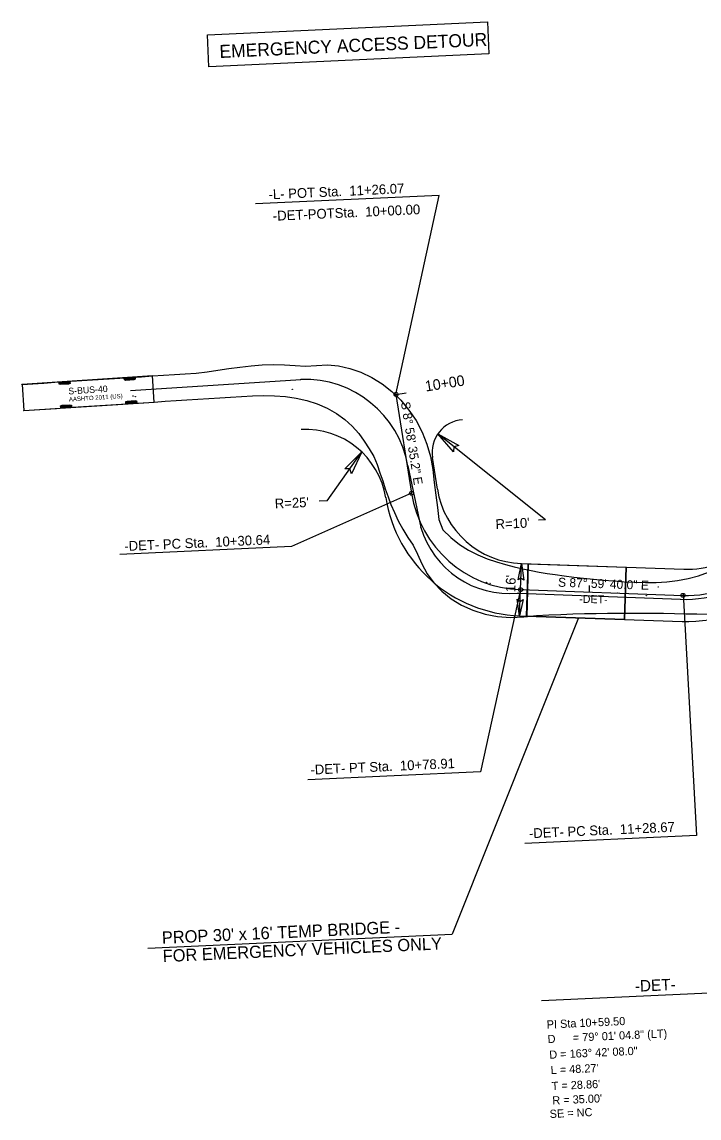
# Model space of a CAD drawing. Extents: x 1191294 to 1803985, y 659552 to 893190.
# Drawn here: x 1191294.4 to 1191501.7, y 892854.1 to 893189.8 of the extents above; entities that cross this region are included whole.
import ezdxf

# ---------------------------------------------------------------- set-up
doc = ezdxf.new("R2010")
doc.units = 0
for name, color, linetype in [('Old_Level_5', 7, 'Continuous'), ('Prop DSN Text', 7, 'Continuous'), ('Prop EOT', 7, 'Continuous'), ('Prop Horizontal Alignment', 7, 'Continuous'), ('Prop Horizontal Alignment Curve and Spiral Data', 7, 'Continuous'), ('Prop Horizontal Alignment Direction Label', 7, 'Continuous'), ('Prop Horizontal Alignment Station Label', 7, 'Continuous'), ('Prop Horizontal Alignment Tick Label', 7, 'Continuous'), ('Prop Horizontal Alignment Tick Large', 7, 'Continuous'), ('Prop Horizontal Alignment Tick Small', 7, 'Continuous'), ('Prop Leader Line Medium', 7, 'Continuous'), ('Prop Roadway Bridge', 7, 'Continuous'), ('Prop Superelevation  Arrow CELL', 7, 'Continuous'), ('Prop Terminator CELL', 7, 'Continuous'), ('Scratch_Level_4', 7, 'Continuous'), ('Scratch_Level_5', 7, 'Continuous'), ('Scratch_Level_9', 7, 'Continuous')]:
    doc.layers.add(name, color=color, linetype=linetype)

msp = doc.modelspace()

# ---------------------------------------------------------------- linework, layer by layer
at = {"layer": 'Old_Level_5'}
msp.add_circle((1191328.43, 893075.21), 0.0417, dxfattribs=at)
at = {"layer": 'Prop DSN Text'}
for p, q in [((1191454.72, 893037.3), (1191421.71, 893063.62)), ((1191387.89, 893043.1), (1191398.43, 893058.11)), ((1191387.89, 893043.1), (1191385.46, 893042.99)), ((1191454.72, 893037.3), (1191452.51, 893037.2))]:
    msp.add_line(p, q, dxfattribs=at)
at = {"layer": 'Prop EOT'}
for p, q in [((1191421.61, 893046.69), (1191420.08, 893056.4)), ((1191447.33, 893023.92), (1191497.07, 893022.18)), ((1191446.78, 893007.93), (1191496.51, 893006.19))]:
    msp.add_line(p, q, dxfattribs=at)
for centre, radius, start, end in [((1191381.15, 893040.04), 25, 9.1923, 92.9116), ((1191429.95, 893057.96), 10, 93.6582, 188.9764), ((1191448.28, 893050.91), 27, 188.9764, 267.9944), ((1191448.28, 893050.91), 43, 188.9764, 267.9944), ((1191498.01, 893049.17), 27, 267.9944, 312.5411), ((1191498.01, 893049.17), 43, 267.9944, 312.5411)]:
    msp.add_arc(centre, radius, start, end, dxfattribs=at)
at = {"layer": 'Prop Horizontal Alignment'}
for p, q in [((1191408.93, 893075.71), (1191413.71, 893045.45)), ((1191447.06, 893015.93), (1191496.79, 893014.19))]:
    msp.add_line(p, q, dxfattribs=at)
for centre, start, end in [((1191448.28, 893050.91), 188.9764, 267.9944), ((1191498.01, 893049.17), 267.9944, 312.5411)]:
    msp.add_arc(centre, 35, start, end, dxfattribs=at)
at = {"layer": 'Prop Horizontal Alignment Station Label'}
for p, q in [((1191422.16, 893136.67), (1191365.93, 893134.1)), ((1191408.93, 893075.71), (1191422.16, 893136.67)), ((1191413.71, 893045.45), (1191376.96, 893029.14)), ((1191376.96, 893029.14), (1191324.41, 893026.74)), ((1191447.06, 893015.93), (1191434.84, 892960.11)), ((1191496.81, 893014.79), (1191500.9, 892940.61)), ((1191434.84, 892960.11), (1191381.98, 892957.69)), ((1191500.9, 892940.61), (1191448.33, 892938.21)), ((1191544.98, 892894.19), (1191453.47, 892890))]:
    msp.add_line(p, q, dxfattribs=at)
msp.add_lwpolyline([(1191351.2, 893185.88), (1191436.93, 893189.8), (1191437.38, 893180.01), (1191351.65, 893176.09)], close=True, dxfattribs=at)
for centre in [(1191408.93, 893075.71), (1191408.93, 893075.71), (1191413.71, 893045.45), (1191447.06, 893015.93), (1191496.79, 893014.19)]:
    msp.add_circle(centre, 0.6, dxfattribs=at)
at = {"layer": 'Prop Horizontal Alignment Tick Large'}
msp.add_line((1191408.93, 893075.71), (1191412.09, 893076.21), dxfattribs=at)
msp.add_line((1191408.93, 893075.71), (1191412.09, 893076.21), dxfattribs=at)
at = {"layer": 'Prop Horizontal Alignment Tick Small'}
msp.add_line((1191468.13, 893015.19), (1191468.2, 893017.19), dxfattribs=at)
at = {"layer": 'Prop Leader Line Medium'}
for p in [(1191464.79, 893007.29), (1191333.01, 892906.14)]:
    msp.add_line(p, (1191426.17, 892910.4), dxfattribs=at)
at = {"layer": 'Prop Roadway Bridge'}
for p, q in [((1191449.43, 893023.85), (1191448.95, 893007.52)), ((1191449.43, 893023.85), (1191479.41, 893022.8)), ((1191478.85, 893006.81), (1191479.41, 893022.8)), ((1191448.87, 893007.86), (1191478.85, 893006.81))]:
    msp.add_line(p, q, dxfattribs=at)
at = {"layer": 'Prop Superelevation  Arrow CELL'}
msp.add_line((1191446.78, 893007.93), (1191447.33, 893023.92), dxfattribs=at)
at = {"layer": 'Prop Terminator CELL'}
for points in [[(1191426.57, 893058.16), (1191421.71, 893063.62), (1191428.17, 893060.11), (1191426.65, 893059.68)], [(1191393.28, 893052.93), (1191398.43, 893058.11), (1191395.32, 893051.45), (1191394.8, 893052.94)], [(1191446.29, 893018.92), (1191447.33, 893023.92), (1191448.05, 893018.83), (1191447.18, 893019.5)], [(1191447.82, 893012.94), (1191446.78, 893007.93), (1191446.06, 893013.03), (1191446.93, 893012.35)]]:
    msp.add_lwpolyline(points, close=True, dxfattribs=at)
at = {"layer": 'Scratch_Level_4'}
msp.add_lwpolyline([(1191449.43, 893023.85), (1191479.41, 893022.8), (1191478.85, 893006.81), (1191448.87, 893007.86)], close=True, dxfattribs=at)
at = {"layer": 'Scratch_Level_5'}
for centre in [(1191329.17, 893075.06), (1191377.19, 893077.26), (1191377.19, 893077.26), (1191436.68, 893018.19), (1191436.68, 893018.19), (1191437.73, 893017.83), (1191437.73, 893017.83), (1191448.04, 893015.89), (1191448.04, 893015.89), (1191476.79, 893014.89), (1191476.79, 893014.89), (1191489.23, 893016.71), (1191489.23, 893016.71)]:
    msp.add_circle(centre, 0.0417, dxfattribs=at)
at = {"layer": 'Scratch_Level_9'}
for p, q in [((1191334.39, 893081.38), (1191294.47, 893078.79)), ((1191294.47, 893078.79), (1191294.99, 893070.81)), ((1191309.12, 893079.53), (1191305.79, 893079.32)), ((1191309.13, 893079.32), (1191305.81, 893079.11)), ((1191309.15, 893079.12), (1191305.82, 893078.9)), ((1191329.08, 893080.83), (1191325.75, 893080.61)), ((1191329.09, 893080.62), (1191325.76, 893080.4)), ((1191329.1, 893080.41), (1191325.78, 893080.19)), ((1191327.66, 893076.93), (1191379.85, 893080.32)), ((1191334.9, 893073.39), (1191334.39, 893081.38)), ((1191334.39, 893081.38), (1191334.39, 893081.38)), ((1191294.99, 893070.81), (1191334.9, 893073.39)), ((1191309.58, 893072.38), (1191306.26, 893072.17)), ((1191309.6, 893072.17), (1191306.27, 893071.96)), ((1191309.61, 893071.96), (1191306.28, 893071.75)), ((1191329.54, 893073.67), (1191326.21, 893073.46)), ((1191329.55, 893073.47), (1191326.23, 893073.25)), ((1191329.57, 893073.26), (1191326.24, 893073.04)), ((1191412.6, 893053.85), (1191416.58, 893034.98)), ((1191446.3, 893014.87), (1191496.01, 893012.99))]:
    msp.add_line(p, q, dxfattribs=at)
for points in [[(1191294.47, 893078.79), (1191297.8, 893079.01), (1191301.12, 893079.22), (1191304.45, 893079.44), (1191307.77, 893079.65), (1191311.1, 893079.87), (1191314.43, 893080.08), (1191317.75, 893080.3), (1191321.08, 893080.52), (1191324.41, 893080.73), (1191327.73, 893080.95), (1191331.06, 893081.16), (1191334.39, 893081.38), (1191334.39, 893081.38), (1191337.73, 893081.59), (1191341.08, 893081.81), (1191344.42, 893082.03), (1191347.77, 893082.27), (1191351.1, 893082.67), (1191354.44, 893083.12), (1191357.8, 893083.63), (1191361.18, 893084.1), (1191364.58, 893084.49), (1191368.01, 893084.76), (1191371.43, 893084.88), (1191374.8, 893084.83), (1191378.02, 893084.53), (1191381.23, 893084.41), (1191384.57, 893084.63), (1191387.93, 893084.76), (1191391.36, 893084.44), (1191394.8, 893083.68), (1191398.2, 893082.49), (1191401.5, 893080.91), (1191404.67, 893078.93), (1191407.65, 893076.59), (1191410.4, 893073.92), (1191412.88, 893070.95), (1191415.06, 893067.7), (1191416.91, 893064.21), (1191418.39, 893060.53), (1191419.49, 893056.69), (1191420.19, 893052.74), (1191420.66, 893048.77), (1191421.14, 893044.91), (1191421.61, 893041.14), (1191422.09, 893037.45), (1191423.32, 893034.3), (1191425.72, 893031.86), (1191428.34, 893029.74), (1191431.15, 893027.99), (1191434.02, 893026.57), (1191436.89, 893025.4), (1191439.7, 893024.42), (1191442.46, 893023.59), (1191445.14, 893022.89), (1191447.75, 893022.29), (1191450.29, 893021.77), (1191452.77, 893021.31), (1191455.19, 893020.91), (1191457.68, 893020.53), (1191460.45, 893020.15), (1191463.34, 893019.8), (1191466.33, 893019.47), (1191469.38, 893019.16), (1191472.49, 893018.87), (1191475.64, 893018.61), (1191478.83, 893018.37), (1191482.05, 893018.18), (1191485.3, 893018.08), (1191488.56, 893018.12), (1191491.83, 893018.31), (1191495.09, 893018.7), (1191498.33, 893019.3), (1191501.52, 893020.14), (1191504.63, 893021.24)], [(1191294.99, 893070.81), (1191298.31, 893071.02), (1191301.64, 893071.24), (1191304.97, 893071.46), (1191308.29, 893071.67), (1191311.62, 893071.89), (1191314.94, 893072.1), (1191318.27, 893072.32), (1191321.6, 893072.53), (1191324.92, 893072.75), (1191328.25, 893072.96), (1191331.58, 893073.18), (1191334.9, 893073.39), (1191334.9, 893073.39), (1191334.9, 893073.39), (1191338.25, 893073.61), (1191341.59, 893073.83), (1191344.94, 893074.05), (1191348.29, 893074.26), (1191351.63, 893074.48), (1191354.98, 893074.7), (1191358.32, 893074.91), (1191361.67, 893075.13), (1191365.02, 893075.3), (1191368.37, 893075.37), (1191371.72, 893075.31), (1191375.06, 893075.05), (1191378.38, 893074.57), (1191381.64, 893073.83), (1191384.83, 893072.8), (1191387.88, 893071.47), (1191390.71, 893069.87), (1191393.27, 893068.02), (1191395.54, 893065.96), (1191397.51, 893063.73), (1191399.24, 893061.42), (1191400.77, 893059.06), (1191402.14, 893056.69), (1191403.18, 893054.22), (1191404.01, 893051.7), (1191404.86, 893049.23), (1191405.65, 893046.77), (1191406.54, 893044.38), (1191407.4, 893041.97), (1191408.47, 893039.58), (1191409.61, 893036.97), (1191411.02, 893034.42), (1191412.51, 893031.86), (1191414.17, 893029.54), (1191415.54, 893026.82), (1191416.86, 893023.81), (1191418.43, 893020.81), (1191420.47, 893017.99), (1191422.95, 893015.42), (1191425.82, 893013.13), (1191429.01, 893011.18), (1191432.49, 893009.6), (1191436.19, 893008.43), (1191440.05, 893007.7), (1191444.02, 893007.42), (1191448.03, 893007.61), (1191451.97, 893008.03), (1191455.75, 893008.2), (1191459.44, 893008.36), (1191463.08, 893008.49), (1191466.65, 893008.59), (1191470.19, 893008.67), (1191473.69, 893008.72), (1191477.16, 893008.75), (1191480.61, 893008.76), (1191484.03, 893008.75), (1191487.45, 893008.72), (1191490.85, 893008.68), (1191494.23, 893008.63), (1191497.62, 893008.56), (1191500.99, 893008.49), (1191504.37, 893008.46)]]:
    msp.add_lwpolyline(points, dxfattribs=at)
for points in [[(1191309.12, 893079.58), (1191309.15, 893079.06), (1191308.69, 893078.88), (1191306.3, 893078.72), (1191305.82, 893078.85), (1191305.79, 893079.37), (1191306.24, 893079.55), (1191308.64, 893079.71)], [(1191329.07, 893080.88), (1191329.11, 893080.36), (1191328.65, 893080.17), (1191326.26, 893080.02), (1191325.78, 893080.14), (1191325.75, 893080.66), (1191326.2, 893080.85), (1191328.6, 893081)], [(1191309.58, 893072.43), (1191309.61, 893071.91), (1191309.16, 893071.73), (1191306.76, 893071.57), (1191306.29, 893071.7), (1191306.25, 893072.22), (1191306.71, 893072.4), (1191309.1, 893072.56)], [(1191329.54, 893073.73), (1191329.57, 893073.21), (1191329.11, 893073.02), (1191326.72, 893072.86), (1191326.24, 893072.99), (1191326.21, 893073.51), (1191326.67, 893073.7), (1191329.06, 893073.85)]]:
    msp.add_lwpolyline(points, close=True, dxfattribs=at)
for centre in [(1191294.47, 893078.79), (1191379.85, 893080.32), (1191379.85, 893080.32), (1191327.66, 893076.93), (1191329.17, 893075.06), (1191377.17, 893077.26), (1191377.17, 893077.26), (1191294.99, 893070.81), (1191412.6, 893053.85), (1191412.6, 893053.85), (1191416.58, 893034.98), (1191416.58, 893034.98), (1191446.3, 893014.87), (1191446.3, 893014.87), (1191447.13, 893015.43), (1191447.13, 893015.43), (1191485.57, 893014.08), (1191485.57, 893014.08), (1191496.01, 893012.99), (1191496.01, 893012.99)]:
    msp.add_circle(centre, 0.0417, dxfattribs=at)
for centre, radius, start, end in [((1191381, 893048.24), 32.09, 10.0621, 92.0463), ((1191443.63, 893042.94), 28.2, 196.4126, 275.4306), ((1191497.32, 893050.39), 37.43, 267.9944, 312.5411)]:
    msp.add_arc(centre, radius, start, end, dxfattribs=at)

# ---------------------------------------------------------------- texts
at = {"layer": 'Prop DSN Text'}
for s, height, rotation, p in [("R=25'", 3, 2.6195, (1191371.89, 893040.77)), ("R=10'", 3, 2.6195, (1191439.47, 893034.48)), ("16'", 3, 87.8664, (1191445.45, 893015.13)), ("PROP 30' x 16' TEMP BRIDGE - ", 3.75, 2.6195, (1191337.36, 892907.47)), ('FOR EMERGENCY VEHICLES ONLY', 3.75, 2.6195, (1191337.61, 892901.85))]:
    msp.add_text(s, height=height, rotation=rotation, dxfattribs=at).set_placement(p)
at = {"layer": 'Prop Horizontal Alignment Curve and Spiral Data'}
for s, height, p in [('-DET-', 3.5, (1191482.13, 892892.76)), ('PI Sta 10+59.50', 2.5, (1191455.12, 892881.5)), ('= 79%%d 01\' 04.8" (LT)', 2.5, (1191463.12, 892877.49)), ('D', 2.5, (1191455.4, 892877.04)), ('D = 163%%d 42\' 08.0"', 2.5, (1191455.91, 892872.25)), ("L = 48.27'", 2.5, (1191456.33, 892867.55)), ("T = 28.86'", 2.5, (1191456.65, 892862.65)), ("R = 35.00'", 2.5, (1191456.85, 892858.24)), ('SE = NC', 2.5, (1191456.03, 892854.12))]:
    msp.add_text(s, height=height, rotation=2.6195, dxfattribs=at).set_placement(p)
at = {"layer": 'Prop Horizontal Alignment Direction Label'}
for s, rotation, p in [('S 8%%d 58\' 35.2" E', 278.9764, (1191410.43, 893073.28)), ('S 87%%d 59\' 40.0" E', 357.9944, (1191458.5, 893016.85))]:
    msp.add_text(s, height=2.75, rotation=rotation, dxfattribs=at).set_placement(p)
at = {"layer": 'Prop Horizontal Alignment Station Label'}
for s, height, p in [('EMERGENCY ACCESS DETOUR', 4, (1191354.98, 893178.74)), ('-L- POT Sta.  11+26.07', 3, (1191369.99, 893135.45)), ('-DET-POTSta.  10+00.00', 3, (1191371.3, 893128.88)), ('-DET- PC Sta.  10+30.64', 3, (1191325.83, 893027.76)), ('-DET- PT Sta.  10+78.91', 3, (1191382.81, 892959.27)), ('-DET- PC Sta.  11+28.67', 3, (1191449.69, 892939.78))]:
    msp.add_text(s, height=height, rotation=2.6195, dxfattribs=at).set_placement(p)
at = {"layer": 'Prop Horizontal Alignment Tick Label'}
msp.add_text('10+00', height=3.25, rotation=8.9764, dxfattribs=at).set_placement((1191418.07, 893076.59))
at = {"layer": 'Prop Leader Line Medium'}
msp.add_text('-DET- ', height=2.45, rotation=358.8899, dxfattribs=at).set_placement((1191464.97, 893011.88))
at = {"layer": 'Scratch_Level_9'}
for s, height, p in [('S-BUS-40', 2, (1191308.7, 893075.71)), ('AASHTO 2011 (US)', 1.3333, (1191308.85, 893073.54))]:
    msp.add_text(s, height=height, rotation=3.7073, dxfattribs=at).set_placement(p)

doc.saveas('drawing.dxf')
